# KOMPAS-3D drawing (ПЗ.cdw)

Views: Вид 1
Referenced files in D:\888\Проектирование\ВЭП\Новая папка\: ПЗ.cdw
Referenced files in \\Server\сетевая_сервер\Борисовский РЭС\ул. Раздольная (ИЖС)\: ПЗ.cdw
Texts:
  Реконструкция ВЛ-0,4 кВ КТП 469 ПС Сетище,  КТП 469 ПС Сетище х. Н. Путь Красненского района Белгородской области
  user
  Normal
  Содержание пояснительной записки:
  1. Исходные данные
  2. Паспорт проекта
  3. Краткая характеристика объекта
  4. Охрана окружающей природной среды
  5. Инновационные решения
  В настоящем рабочем проекте все технические решения по
  сооружениям, конструкциям, оборудованию и технической части
  приняты и разработаны в полном соответствии с действующими на
  дату выпуска проекта нормами и правилами, включая правила
  пожаро-взрывобезопасности.
  При соблюдении правил технической эксплуатации, а так же
  требований техники безопасности и пожаро-взрывобезопасности,
  эксплуатация сооружений по данному проекту безопасна.
  Проект разработан на основе применения утверждённых типовых
  конструкций и оборудования серийного заводского изготовления и не
  содержит охраноспособных технических решений, в связи с этим
  проверка проекта на патентную чистоту и патентоспособность не
  проводилась.
  Наименование характеристики
  Код
  Показатели характеристики
  2. Электротехнические решения
  Задание на проектирование
  Заказчик проекта
  Строительная организация
  Эксплуатационная организация
  Тип воспроизводства
  Адрес строительства
  Год строительства
  Дата выполнения проекта
  Напряжение
  Расчетные электрические нагрузки,
  кВт
  Допустимые потери напряжения, %
  Допустимые отклонения напряжения,
  Устройство заземляющих устройств
  выполняется по т. п. 3-407-150, Ом
  Новое
  строительство
  № Р-20 от "15" апреля 2016 г.
  Филиал
  ПАО "МРСК Центра" - "Белгородэнерго"
  По тендеру
  Красненский  РЭС
  Реконструкция
  Белгородская область,
  Красненский район, х. Н. Путь
  по ветру
  Нормативная стенка гололеда, мм
  Нормативная скорость ветра, м/с
  Тип провода, кабеля:
  марка
  длина
  Протяженность линии м
  Стойка:
  тип
  количество, шт.
  Взамен пришедших в негодность
  по гололеду
  Климатические условия:
  Материал опор
  СИП-3 1х70
  АПвПу 1х120/25-10
  АВБбШв 4х35
  АВБбШв 4х120
  СИП-2 3х70+1х70
  СИП-2 3х70+1х70+1х16
  СИП-4 2х16
  СИП-4 4х25
  СИП-4 4х16
  СВ95-3
  СВ110-5
  Всего по сводному расчету, т. руб.
  Всего, шт.
  повышенных, шт
  промежуточно-угловых, шт.
  с анкерным креплением, шт.
  промежуточных, шт.
  Количество опор:
  С совместной подвеской провода
  предназначена для передачи и распределения электроэнергии потребителей
  3-й категории, в х. Н.Путь, Красненского района Белгородской области.
  протяженностью 0,462км.
  Выполняется реконструкция  ВЛ-0,4 кВ №2  от КТП-469 ПС Сетище
  протяженностью 0,471 км.
  Выполняется реконструкция  ВЛ-0,4 кВ №3  от КТП-469 ПС Сетище
  протяженностью 0,481 км.
  Выполняется реконструкция  ВЛ-0,4 кВ №4  от КТП-469 ПС Сетище
  протяженностью 0,490 км.
  Выполняется строительство КЛ-0,4 кВ от проект. СТП до проект. опоры №3.1
  протяженностью 0,048 км
  Выполняется строительство КЛ-0,4 кВ от проект. СТП до проект. опоры №4.1
  протяженностью 0,064 км
  км из них в кабельном исполнении 0,227 км
  Выполняется замена КТП 469 ПС Сетище на СТП 10/0,4 кВ. Трансформатор
  принят масляный герметичного исполнения мощностью 63 кВА, типа ТМГ-63
  сечением токоведущей жилы 70 мм .
  сечением токоведущей жилы 120 мм  и сечением экрана 25мм
  ПВХ, токоведущая жила - алюминевая, сечением 120 мм  кабель наружнего
  освещения четырех жильный марки АВБбШв 4х35 с изоляцией из ПВХ,
  токоведущая жила - алюминевая, сечением 35 мм .
  мм от кабеля укладывается сигнальная лента ЛСЭ-300.
  3х70+1х70+1х16 , СИП-2 3х70+1х70 с сечением токоведущей жилы 70 мм  и
  жилой наружнего освещения сечением 16 мм .
  проводом марки СИП-4 2х16, СИП-4 2х16, СИП-4 4х16 с сечением токоведущих
  полимерная с оболочкой из кремнийорганической резины, степень загрязнения
  IV по ГОСТ 9920 (удельная проводимость слоя загрязнения не менее 30 мкСм).
  Стойки опор ВЛИ-0,4 кВ приняты ж/б типа СВ95-3, СВ110-5.
  Опоры линии электропередач устанавливаются в сверленные котлованы,
  используя бурильно-крановую машину на автоходу типа БМ-202.
  4. Охрана окружающей среды
  Раздел проекта «Охрана окружающей среды» разработан в соответствии
  - Законом Российской Федерации «0 Санитарно-эпидемиологическом
  благополучии населения от 19.04.91г.»
  - Земельным Кодексом Российской Федерации от 25.04.91г.
  - Законом Российской Федерации «Об инвестиционной деятельности в
  Российской Федерации» от 26.06.92г.
  - Законом Российской Федерации «0 плате за землю».
  - Законом Российской Федерации «Об окружающей природной среде»
  от 19.12.91г.
  - Законом Российской Федерации «0 недрах» от 21.02.92г,
  - СНиПом 02.01.82г. «Строительная климатология и геофизика».
  - ГОСТом 17.2.3.02-78 «Охрана природы. Атмосфера. Правила
  установления допустимых выбросов вредных веществ промышленными
  предприятиями!
  - СаНПиНом 2.2.1/2.1.1.567-96 «Санитарные защитные зоны и
  санитарнаяклассификация предприятий, сооружений и иных объектов».
  - ОНД-90 «Руководство по контролю источников загрязнения
  атмосферы»ВНИИ охраны природы и заповедного дела Министерства
  природопользования и охраны окружающей среды 1991г. выпуск 1,2.
  - Справочно-информационными материалами Главного управления
  государственной экологической экспертизы, Москва 1997г.
  - Рекомендациями по основным вопросам воздушно-охранной
  деятельности. Москва 1995г.
  - РД51-100-85 «Руководство по нормированию выбросов загрязняющих
  веществ в атмосферу на объектах транспорта и хранения газа».
  4.2. Оценка воздействия на окружающую среду
  технологических процессов.
  4.2.1. Краткая  характеристика  физико-географических и климатических
  условий района строительства
  Проектируемая трасса ВЛ расположено в пределах Средне-Русской
  возвышенности, которая представляет  собой пологоволнистую,
  большей частью открытию равнину расчлененную на отдельных участках
  балками и оврагами.
  Вследствие большой отдаленности от морей и океанов, климат
  района прохождения трассы характеризуется значительной
  континентальностью, солнечным продолжительным летом и
  относительно холодной зимой.
  Средняя годовая температура воздуха равна 5° С.
  Наиболее  холодным месяцем в году является январь, средняя
  температура его минус 25° С, абсолютная минимальная температура
  понижалась до -38°С. Наиболее  теплый месяц в году - июль, средняя
  температура его 23°С, абсолютная максимальная  температура
  повышалась до 38° С.
  Снежный покров устанавливается в середине первой декады
  декабря,максимальная высота снега за зиму достигается 41 см.
  Средняя месячная скорость ветра изменяется в пределах 3-5 м/с, при
  этом зимой и  в  переходные  периоды скорость  ветра  увеличивается,
  летом -  уменьшается. Скорость  ветра повторяемостью один  раз  в
  Грозовая деятельность  района  характеризуется числом дней с грозой
  40 и средней продолжительностью гроз, ровной 80-100 часа.
  4.2.2. Оценка природохозяйственной ценности территории в зоне
  строительства
  Выбор  трассы ВЛ произведен  в  соответствии с «Положением о
  порядке возбуждения и рассмотрения ходатайств о предоставлении
  земельных участков  для государственных и общественных нужд».
  При выборе  оптимального варианта  трассы ВЛ
  учитывались предполагаемые убытки землепользователей, связанных с:
  - изъятием участков земли под опоры в постоянное пользование:
  - изъятием полос земли вдоль  трассы ВЛ на  период  ее
  строительства(во  временное  пользование).
  Характеристика  угодий,  по  которым проходит  трасса ВЛ,  приведена в
  ведомости отвода земли в постоянное и временное пользование.
  4.2.3  Оценка  воздействия на окружающую  воздушную  среду.
  Технологический процесс передачи и распределения электроэнергии
  является безотходным и не сопровождается вредными выбросами в
  окружающую  среду. В связи с этим, воздушно-охранных мероприятий
  настоящим проектом не  предусматривается.
  4.2.4 Оценка воздействия на окружающую среду водопользователя.
  Учитывая  сказанное в п.4.2.3, технологический процесс не
  сопровождается выбросами и в водную среду. В связи с этим,
  водоохранных мероприятии настоящим проектом не предусматривается.
  4.2.5 Оценка воздействия на окружающую среду землепользователя.
  Трасса проектируемой ВЛ не пересекает зарегистрированных
  месторождении полезных ископаемых, не проходит по территориям
  природоохранительного назначения.
  Во временное пользование, на период строительства, для монтажа
  опор и проводов предусмотрен отвод земли общей площадью   га. После
  сооружения ВЛ земельные участки, временно используемые при
  строительстве, должны быть приведены в состояние, пригодное для
  проведения сельскохозяйственных робот.
  Площадь плодородных земель (пашня, сенокос, пастбище), отводимых
  в постоянное пользование для установки опор, определена в
  соответствии с «Нормами отвода земель для электрических сетей
  напряжением 0,38-750кВ (14278тм-т1)» и составляет         га.
  В процессе установки опор, снимается плодородный слой с земельных
  участков, который использовался для строительства, он должен быть
  применен для рекультивации нарушенных земель согласно ГОСТ
  17.4.3.02.-85 (Охрана природы. Почвы. Требования к охране
  плодородного слоя почвы при производстве земельных робот).
  Специальной площадки для хранения плодородного слоя не
  предусматривается из-за небольшого объема (расстояние между
  опорами 30 м и менее, площадь земли под стойку опоры составляет
  После сооружения ВЛ земельные участки, временно используемые при
  проведения сельскохозяйственных робот (в первоначальное состояние
  при строительстве в черте населенного пункта).
  Затраты на освоение земли, взамен изымаемой в постоянное и
  временное пользование, учтены сметой в соответствии с «Нормами
  стоимости освоения новых земель, изымаемых для
  сельскохозяйственных нужд и о порядке использования средств,
  предназначенных для возмещения потерь с/х производства,
  утвержденными постановлением Совета Министров Правительства
  Российской Федерации от 28 января 1993г. N 77. г.Москва».
  ООО "СК РЭС"
  В целях реализации политики инновационного развития и
  осуществления процесса внедрения перспективных технических
  решений, на основании распоряжения № ЦА/25/94-р от 02.06.2015
  "О реализации политики инновационного развития,
  энергосбережения", для повышения надежности электроснабжения в
  данном проекте применены инновационные технологии.
  на полезную модель №133983 "Столбовая трансформаторная
  подстанция".
  ориентированную опору высоковольтной воздушной линии, на
  которой установлен силовой трансформатор мощностью от 25 до 100
  кВА включительно. В качестве опоры могут использоваться стойки
  ж/б, из металла, из дерева. На стойке установлен силовой
  трансформатор, выполненый с системой охлаждения (оребрение),
  которая обеспечивает нормальный тепловой режим активной части
  трансформатора и её изоляции на протяжении всего срока
  эксплуатации. Силовой трансформатор в верхней части корпуса,
  имеет захватывающий элемент для его подвески и крепления на
  вертикально ориентированной опоре. СТП может являться как
  элементов ВЛ 6-10 кВ (промежуточная опора ВЛ), так и отдельно
  стоящей, не являющейся элементом ВЛ. На вертикально
  ориентированной опоре СТП устанавливают щит РУНН с отдельным
  отсеком для АСКУЭ, кронштейны для крепления провода СИП-2.
  Столбовая трансформаторная подстанция
  ед.
  изм.
  шт.
  количество
  для подписи
  POLYLINE_STYLE_0.30_RGB_0_0_0
  CONTI_RGB_0_0_0_THICK_0.3
  Разработ.
  Шубин
  Александрова
  Н. Контр
  Кабаков
  ГИП
  Реконструкция ВЛ-0,4 кВ КТП 469 ПС Сетище,
  КТП 469 ПС Сетище х. Н. Путь Красненского района Белгородской области
  Пояснительная записка
  Реконструкция ВЛ-0,4 кВ КТП 469 ПС Сетище, -
  Рабоч. чертеж зданий и сооруж. ГОСТ Р 21.1101-2009 Ф3.1
  Лит-Масса-Масштаб
  Материал-Предприятие
  Стадия
  Лист
  Листов
  Изм.
  Кол.уч.
  №док.
  Подп.
  Дата
  Изменение
  Номер документа
  Подпись
  Обозначение документа
  Наименование предприятия, в состав которого входит здание (сооружение)
  Наименование здания (сооружения)
  Порядковый номер листа
  Количество листов в документе
  Должность подписавшего
  Наименование изображения
  Индекс предприятия, выпускающего документ
  Рабоч. чертеж зданий и сооруж. ГОСТ 21.101-97 Ф3.
  Текст. строит. докум. Посл. листы. ГОСТ 2013.
  Порядковый номер документа
  Текст. строит. докум. Посл. листы. ГОСТ Р 21.1101-2009 Ф6.
Dimensions and other numbers on the sheet: 31-135/16-РЭС.ПЗ; 1; 1.1; 1.2; 1.3; 1.4; 1.5; 1.6; 1.7; 1.8; 2.1; 2.2; 2.3; 2.4; 2.5; 2; 3; 4; 2016 г.; 10/0,4; 4,8; 5; 6; 7; 8; 0,4; 25; 36; 101; 768; 149; 488; 1658; 859; 64; 148; 2406; 93; 11; 10; 9; 0.38 и 10 кВ; 73; 21; 50; 4.1. Общие данные; 25лет- 29 м/с.; 1кв.м.).; 0.3; 1:1; 10.16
